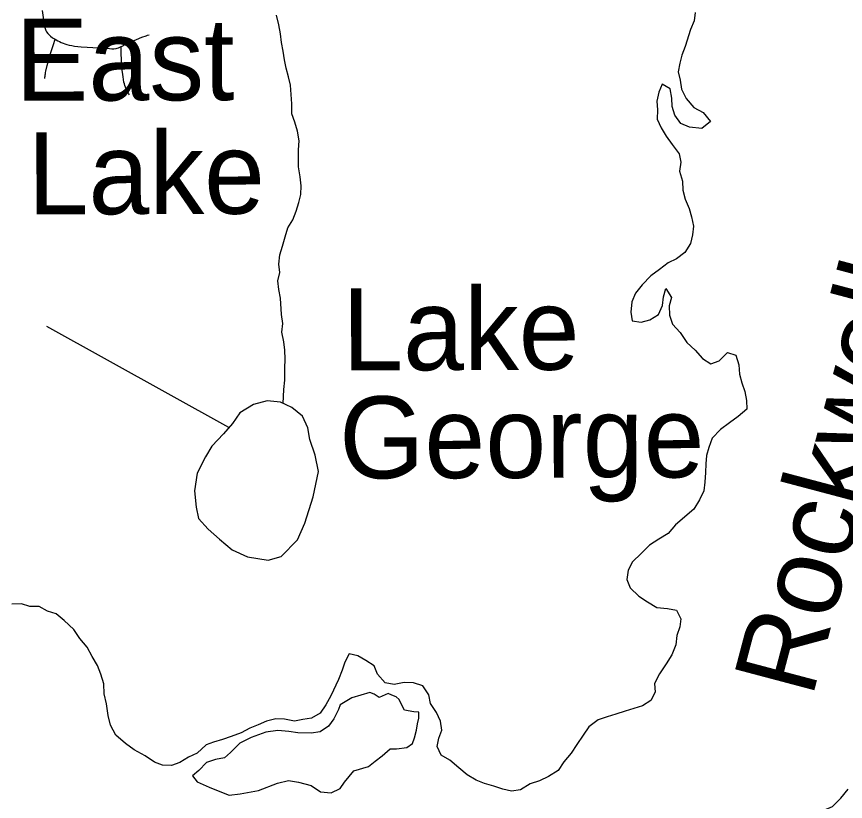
# Model space of a CAD drawing. Extents: x 0 to 34, y 0 to 22.
# Drawn here: x 3.589 to 4.548, y 16.216 to 17.124 of the extents above; entities that cross this region are included whole.
import ezdxf

# ---------------------------------------------------------------- set-up
doc = ezdxf.new("R2010")
doc.units = 0
for name, color, linetype in [('GM_X_Major_Lake', 7, 'Continuous'), ('GM_X_Major_Lake_Text', 7, 'Continuous'), ('GM_X_Minor_Lake', 7, 'Continuous'), ('GM_X_Minor_Lake_Text', 7, 'Continuous'), ('GM_X_Minor_River', 7, 'Continuous'), ('GM_X_Township_Road', 7, 'Continuous')]:
    doc.layers.add(name, color=color, linetype=linetype)

msp = doc.modelspace()

# ---------------------------------------------------------------- linework, layer by layer
at = {"layer": 'GM_X_Major_Lake'}
msp.add_line((3.84792, 16.22481), (3.86946, 16.22877), dxfattribs=at)
for points in [[(4.37448, 17.12836), (4.37342, 17.11887)], [(4.37342, 17.11887), (4.36896, 17.10898), (4.36305, 17.08921), (4.35897, 17.07932), (4.35677, 17.06982), (4.35496, 17.05995), (4.35693, 17.0501), (4.35852, 17.03988), (4.3639, 17.02892), (4.37307, 17.01876), (4.38371, 17.01277), (4.39212, 17.0026), (4.38197, 16.99418)], [(4.38197, 16.99418), (4.36795, 16.99596), (4.3577, 17.00006), (4.35081, 17.00986), (4.34771, 17.0197), (4.34763, 17.02956), (4.34565, 17.04016), (4.33614, 17.04577), (4.33243, 17.03626), (4.33025, 17.02601), (4.3307, 17.01577), (4.33041, 17.00515), (4.33503, 16.99533), (4.34078, 16.98551), (4.34767, 16.97571), (4.35608, 16.96516), (4.35767, 16.95531), (4.35624, 16.94506), (4.35974, 16.93333), (4.36019, 16.92309), (4.36293, 16.9125), (4.36755, 16.90192), (4.37028, 16.89208), (4.37263, 16.88148), (4.3712, 16.87123), (4.369, 16.86135), (4.36265, 16.85107), (4.35287, 16.84379), (4.34307, 16.83916), (4.33329, 16.8315), (4.32313, 16.82384), (4.31299, 16.81352), (4.30549, 16.80398), (4.30103, 16.79409), (4.29999, 16.78195), (4.30158, 16.7721), (4.31181, 16.77028), (4.32201, 16.77302), (4.33218, 16.77916), (4.33664, 16.78981), (4.3377, 16.79968), (4.34065, 16.80918), (4.34717, 16.799), (4.34422, 16.78912), (4.34468, 16.7785), (4.34816, 16.76829), (4.35694, 16.7585), (4.36498, 16.74681), (4.37451, 16.73816), (4.38292, 16.72836), (4.39243, 16.72237), (4.40224, 16.72586), (4.412, 16.73541), (4.42149, 16.73208), (4.42498, 16.72111), (4.42583, 16.71012), (4.42855, 16.70028), (4.43204, 16.69007), (4.43401, 16.67984), (4.43409, 16.66999), (4.42432, 16.66119), (4.41416, 16.65391), (4.40362, 16.64624), (4.39424, 16.63631), (4.39016, 16.62566), (4.38758, 16.61616), (4.3869, 16.60667), (4.38622, 16.59643), (4.38555, 16.58543), (4.38449, 16.57556), (4.37928, 16.5649), (4.37293, 16.55424), (4.35188, 16.53587), (4.34325, 16.52595), (4.33233, 16.51941), (4.32179, 16.51251), (4.31202, 16.50295), (4.30188, 16.49339), (4.29704, 16.4835), (4.29523, 16.47286), (4.29909, 16.46304), (4.30938, 16.45364), (4.31927, 16.44689), (4.32992, 16.44052), (4.34242, 16.43911), (4.35303, 16.43729), (4.35803, 16.42747), (4.35659, 16.41798), (4.35326, 16.40809), (4.35221, 16.39747), (4.34738, 16.38568), (4.34103, 16.37539), (4.33318, 16.36357), (4.32758, 16.35253), (4.32804, 16.34268), (4.3232, 16.33278), (4.3134, 16.32664), (4.30359, 16.32353), (4.29339, 16.32042), (4.28282, 16.31692), (4.27263, 16.31419)], [(3.80887, 16.28177), (3.79835, 16.27183), (3.78817, 16.2672), (3.77838, 16.26106), (3.76856, 16.25757), (3.75834, 16.25825), (3.74885, 16.26159), (3.73819, 16.26909), (3.72527, 16.27581), (3.71537, 16.28332), (3.70432, 16.29272), (3.69818, 16.30442), (3.69544, 16.3154), (3.69344, 16.32903), (3.6907, 16.34077), (3.69023, 16.35214), (3.68674, 16.36349), (3.68288, 16.37332), (3.67674, 16.38389), (3.67098, 16.39446), (3.66257, 16.40463), (3.65568, 16.4152), (3.64462, 16.42535), (3.6351, 16.43324), (3.62523, 16.4362), (3.61535, 16.44143), (3.60475, 16.44173), (3.59527, 16.44469), (3.58392, 16.44422)], [(4.27263, 16.31419), (4.26206, 16.31069), (4.25153, 16.30265), (4.24479, 16.29274), (4.23768, 16.28206), (4.23095, 16.27215), (4.22232, 16.26185), (4.21597, 16.25194), (4.20467, 16.24502), (4.19449, 16.24002), (4.18354, 16.23652), (4.17224, 16.22961), (4.16207, 16.228), (4.1518, 16.23021), (4.14155, 16.23392), (4.13055, 16.23687), (4.12105, 16.24096), (4.11079, 16.24695), (4.10088, 16.25522), (4.0906, 16.26386), (4.08071, 16.26985), (4.07609, 16.27967), (4.07791, 16.28917), (4.08124, 16.29867), (4.07964, 16.3089), (4.07502, 16.3191), (4.06813, 16.32929), (4.06616, 16.33951), (4.05927, 16.34969), (4.04864, 16.3534), (4.03766, 16.3537), (4.02633, 16.35133), (4.01572, 16.35315), (4.00693, 16.36332), (4.00307, 16.37315), (3.99356, 16.37914), (3.98405, 16.38475), (3.9742, 16.38695), (3.96897, 16.37743), (3.96602, 16.36793), (3.96194, 16.35728), (3.953, 16.33825), (3.94703, 16.32797), (3.94067, 16.31844), (3.9305, 16.31229), (3.92067, 16.31108), (3.91084, 16.3091), (3.89947, 16.31129), (3.88925, 16.31159), (3.87868, 16.30886), (3.86887, 16.30461), (3.85906, 16.30074), (3.84926, 16.29536), (3.83756, 16.29147), (3.82774, 16.28798), (3.81717, 16.28487), (3.80887, 16.28177)], [(3.86946, 16.22877), (3.89135, 16.23729), (3.90381, 16.24042), (3.91556, 16.23861), (3.93035, 16.23456), (3.94101, 16.22743), (3.95351, 16.22601), (3.96369, 16.23102), (3.96893, 16.23865), (3.97942, 16.25162), (3.99641, 16.25668), (4.00431, 16.26281), (4.01221, 16.26894), (4.02161, 16.27698), (4.0288, 16.27703), (4.0409, 16.27864), (4.0473, 16.28324), (4.0499, 16.28971), (4.0521, 16.29845), (4.05318, 16.30604), (4.05464, 16.3125), (4.05458, 16.31932), (4.04891, 16.31966), (4.03829, 16.32185), (4.03483, 16.32827), (4.03214, 16.33394), (4.02871, 16.33732), (4.02339, 16.33918), (4.01922, 16.34104), (4.00903, 16.33641), (4.00295, 16.34016), (3.99801, 16.34201), (3.97724, 16.33616), (3.96368, 16.32772), (3.96183, 16.32239), (3.95624, 16.31173), (3.95025, 16.30334), (3.94046, 16.29682), (3.93025, 16.29523), (3.91474, 16.29549), (3.9045, 16.29692), (3.89163, 16.29834), (3.87764, 16.29633), (3.86066, 16.29014), (3.84784, 16.28359), (3.83695, 16.27289), (3.8298, 16.26677), (3.8196, 16.26479), (3.80903, 16.2613), (3.8004, 16.25213), (3.79288, 16.24563), (3.79823, 16.23884), (3.81228, 16.23288), (3.82633, 16.22692), (3.83544, 16.22358), (3.84792, 16.22481)], [(4.49543, 16.1851), (4.50671, 16.19428), (4.51344, 16.20495), (4.52327, 16.20617), (4.53346, 16.21042), (4.54284, 16.21997), (4.55147, 16.23028)]]:
    msp.add_lwpolyline(points, dxfattribs=at)
at = {"layer": 'GM_X_Minor_Lake'}
msp.add_line((3.80777, 16.61469), (3.79846, 16.59566), dxfattribs=at)
msp.add_lwpolyline([(3.79846, 16.59566), (3.79521, 16.57554), (3.79725, 16.55659), (3.8, 16.54334), (3.81108, 16.53092), (3.82404, 16.51964), (3.83889, 16.50724), (3.85637, 16.49904), (3.88062, 16.49506), (3.89535, 16.49934), (3.9145, 16.51883), (3.92305, 16.53785), (3.93265, 16.56826), (3.93886, 16.59789), (3.93493, 16.61644), (3.92873, 16.63459), (3.92635, 16.64822), (3.92019, 16.66183), (3.908, 16.67159), (3.8947, 16.67793), (3.87918, 16.67933), (3.86331, 16.67504), (3.84749, 16.66543), (3.83926, 16.65324), (3.82876, 16.6414), (3.81525, 16.62688), (3.80777, 16.61469)], dxfattribs=at)
at = {"layer": 'GM_X_Minor_River'}
for points in [[(3.8977, 16.6765), (3.89875, 16.69238), (3.8998, 16.70338), (3.8997, 16.71703), (3.89999, 16.72765), (3.89991, 16.73789), (3.8987, 16.74774), (3.89634, 16.75872), (3.89739, 16.76896), (3.8958, 16.77919), (3.8949, 16.79814), (3.89292, 16.80836), (3.89171, 16.81821), (3.89391, 16.82771), (3.89269, 16.83756), (3.89413, 16.84819), (3.89707, 16.85845), (3.90002, 16.86909), (3.90334, 16.87936), (3.90894, 16.88888), (3.91303, 16.89877), (3.91598, 16.90865), (3.91818, 16.91815), (3.91848, 16.92801), (3.91764, 16.93862), (3.91566, 16.94998), (3.9155, 16.9697), (3.91618, 16.97995), (3.91458, 16.99131), (3.91147, 17.00152), (3.90799, 17.01135), (3.9079, 17.02273), (3.90705, 17.03372), (3.90622, 17.04433), (3.90386, 17.05417), (3.90114, 17.06401), (3.89917, 17.07385), (3.89796, 17.0837), (3.89599, 17.09393), (3.89477, 17.10378), (3.8928, 17.11438), (3.89006, 17.12536)], [(3.83504, 16.64848), (3.62454, 16.76533)]]:
    msp.add_lwpolyline(points, dxfattribs=at)
at = {"layer": 'GM_X_Township_Road'}
for points in [[(3.61896, 17.13076), (3.62078, 17.11722), (3.62116, 17.11486), (3.6218, 17.11235), (3.62249, 17.10983), (3.62329, 17.10767), (3.62416, 17.10605), (3.6257, 17.10413), (3.62678, 17.10299), (3.62868, 17.10119), (3.63112, 17.09935), (3.63408, 17.09756), (3.63726, 17.09578), (3.6391, 17.09483), (3.64117, 17.09389), (3.6433, 17.09307), (3.64523, 17.09233), (3.64763, 17.09154), (3.65042, 17.09092), (3.6532, 17.09036), (3.65638, 17.08975), (3.66012, 17.08924), (3.6643, 17.08885), (3.68464, 17.08752), (3.69704, 17.08678), (3.6997, 17.08664), (3.70199, 17.08652), (3.70443, 17.08678), (3.70594, 17.08716), (3.70742, 17.08773), (3.71025, 17.08906), (3.71168, 17.08973), (3.71595, 17.09182), (3.72821, 17.09722), (3.73445, 17.09999), (3.73913, 17.10168), (3.74068, 17.10215), (3.74274, 17.1026)], [(3.62203, 17.05227), (3.62217, 17.05363), (3.62229, 17.05472), (3.62253, 17.05634), (3.62273, 17.05769), (3.62296, 17.05926), (3.6232, 17.06082), (3.62467, 17.06741), (3.62747, 17.07744), (3.63204, 17.09141), (3.63408, 17.09756)], [(3.72017, 17.0334), (3.71934, 17.03464), (3.71835, 17.03611), (3.71746, 17.03794), (3.71633, 17.04029), (3.71559, 17.04202), (3.71477, 17.04398), (3.71408, 17.04603), (3.7136, 17.04798), (3.71257, 17.05399), (3.71134, 17.0644), (3.71095, 17.0715), (3.71048, 17.08346), (3.71025, 17.08906)]]:
    msp.add_lwpolyline(points, dxfattribs=at)

# ---------------------------------------------------------------- texts
at = {"layer": 'GM_X_Major_Lake_Text'}
msp.add_text('Rockwell', height=0.094727, rotation=75.17416, dxfattribs=at).set_placement((4.50967, 16.33473))
at = {"layer": 'GM_X_Minor_Lake_Text'}
for s, height, rotation, p in [('East', 0.09474, 0.17392, (3.58809, 17.02646)), ('Lake', 0.094741, 0.17406, (3.60219, 16.89502)), ('Lake', 0.09474, 0.17387, (3.9662, 16.7146)), ('George', 0.094741, 0.17323, (3.96274, 16.58969))]:
    msp.add_text(s, height=height, rotation=rotation, dxfattribs=at).set_placement(p)

doc.saveas('drawing.dxf')
